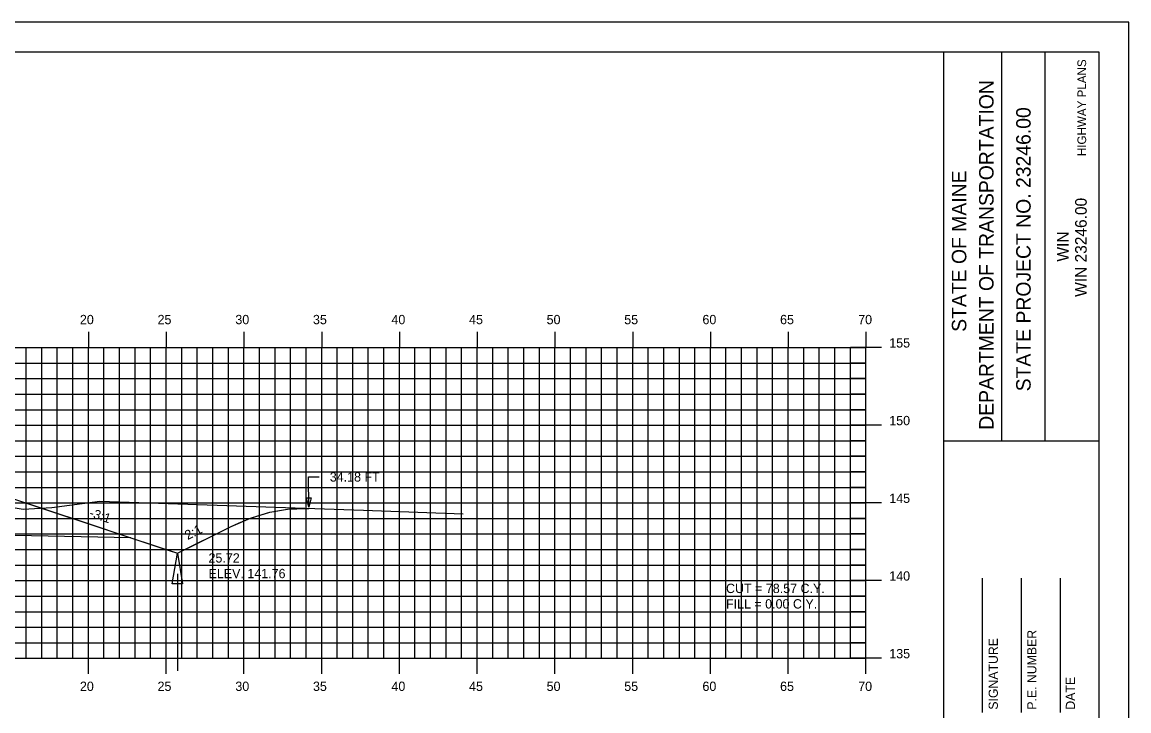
# Model space of a CAD drawing. Extents: x 1144751 to 1144921, y 608981 to 609091.
# Drawn here: x 1144849.4 to 1144920.5, y 609047 to 609091.3 of the extents above; entities that cross this region are included whole.
import ezdxf

# ---------------------------------------------------------------- set-up
doc = ezdxf.new("R2010")
doc.units = 0
for name, color, linetype in [('ANNOTATION', 7, 'Continuous'), ('BORDER', 7, 'Continuous'), ('D_Drainage_Ditch_Line', 7, 'Continuous'), ('D_Roadway_SlopeLines', 7, 'Continuous'), ('D_Roadway_SubGrade', 7, 'Continuous'), ('D_Text_Standard', 7, 'Continuous'), ('H_V ANNOTATION', 7, 'Continuous'), ('HIGHWAY_TITLE', 7, 'Continuous'), ('MAJOR', 7, 'Continuous'), ('MINOR', 7, 'Continuous'), ('PLOT BOUNDARY', 7, 'Continuous'), ('S_Roadway_Centerline', 7, 'Continuous')]:
    doc.layers.add(name, color=color, linetype=linetype)

msp = doc.modelspace()

# ---------------------------------------------------------------- linework, layer by layer
msp.add_lwpolyline([(1144848.619, 609060.668), (1144853.41, 609059.072), (1144856.342, 609058.094), (1144858.203, 609057.474), (1144859.342, 609057.094), (1144860.653, 609057.749), (1144862.796, 609058.821), (1144863.27, 609059.026), (1144864.046, 609059.362), (1144864.52, 609059.504), (1144865.296, 609059.737), (1144865.77, 609059.816), (1144866.546, 609059.945), (1144867.02, 609059.96), (1144867.796, 609059.986)])
at = {"layer": 'BORDER'}
for p, q in [((1144908.619, 608984.335), (1144908.619, 609089.335)), ((1144912.348, 609064.332), (1144912.348, 609089.332)), ((1144915.143, 609064.332), (1144915.143, 609089.332)), ((1144908.62, 609064.329), (1144918.619, 609064.329)), ((1144911.119, 609046.838), (1144911.119, 609055.485)), ((1144913.619, 609046.838), (1144913.619, 609055.485)), ((1144916.119, 609046.838), (1144916.119, 609055.485))]:
    msp.add_line(p, q, dxfattribs=at)
msp.add_lwpolyline([(1144758.619, 608984.335), (1144918.619, 608984.335), (1144918.619, 609089.335), (1144758.619, 609089.335)], close=True, dxfattribs=at)
at = {"layer": 'D_Drainage_Ditch_Line'}
msp.add_line((1144859.342, 609055.782), (1144859.342, 609049.538), dxfattribs=at)
msp.add_lwpolyline([(1144859.67, 609055.125), (1144859.014, 609055.125), (1144859.342, 609057.094)], close=True, dxfattribs=at)
at = {"layer": 'D_Roadway_SlopeLines'}
for points in [[(1144859.342, 609057.094), (1144862.796, 609058.821), (1144864.046, 609059.362), (1144865.296, 609059.737), (1144866.546, 609059.945), (1144867.796, 609059.986)], [(1144856.342, 609058.094), (1144859.342, 609057.094)]]:
    msp.add_lwpolyline(points, dxfattribs=at)
at = {"layer": 'D_Roadway_SubGrade'}
msp.add_lwpolyline([(1144844.619, 609060.412), (1144844.619, 609060.578), (1144848.619, 609060.418), (1144848.619, 609060.668), (1144848.619, 609060.668), (1144856.342, 609058.094), (1144844.619, 609058.328)], close=True, dxfattribs=at)
at = {"layer": 'D_Text_Standard'}
msp.add_lwpolyline([(1144867.796, 609060.071), (1144867.781, 609062.007), (1144868.461, 609062.007)], dxfattribs=at)
msp.add_lwpolyline([(1144867.796, 609060.071), (1144867.646, 609060.652), (1144867.937, 609060.654)], close=True, dxfattribs=at)
at = {"layer": 'MAJOR'}
for p, q in [((1144853.619, 609071.337), (1144853.619, 609070.335)), ((1144858.619, 609071.337), (1144858.619, 609070.335)), ((1144863.619, 609071.337), (1144863.619, 609070.335)), ((1144868.619, 609071.337), (1144868.619, 609070.335)), ((1144873.619, 609071.337), (1144873.619, 609070.335)), ((1144878.619, 609071.337), (1144878.619, 609070.335)), ((1144883.619, 609071.337), (1144883.619, 609070.335)), ((1144888.619, 609071.337), (1144888.619, 609070.335)), ((1144893.619, 609071.337), (1144893.619, 609070.335)), ((1144898.619, 609071.337), (1144898.619, 609070.335)), ((1144903.619, 609071.337), (1144903.619, 609070.335)), ((1144763.619, 609070.335), (1144903.619, 609070.335)), ((1144763.619, 609070.335), (1144903.619, 609070.335)), ((1144853.619, 609050.335), (1144853.619, 609070.335)), ((1144858.619, 609050.335), (1144858.619, 609070.335)), ((1144863.619, 609050.335), (1144863.619, 609070.335)), ((1144868.619, 609050.335), (1144868.619, 609070.335)), ((1144873.619, 609050.335), (1144873.619, 609070.335)), ((1144878.619, 609050.335), (1144878.619, 609070.335)), ((1144883.619, 609050.335), (1144883.619, 609070.335)), ((1144888.619, 609050.335), (1144888.619, 609070.335)), ((1144893.619, 609050.335), (1144893.619, 609070.335)), ((1144898.619, 609050.335), (1144898.619, 609070.335)), ((1144904.621, 609070.335), (1144902.617, 609070.335)), ((1144903.619, 609050.335), (1144903.619, 609070.335)), ((1144903.619, 609050.335), (1144903.619, 609070.335)), ((1144763.619, 609065.335), (1144903.619, 609065.335)), ((1144904.621, 609065.335), (1144902.617, 609065.335)), ((1144763.619, 609060.335), (1144903.619, 609060.335)), ((1144904.621, 609060.335), (1144902.617, 609060.335)), ((1144763.619, 609055.335), (1144903.619, 609055.335)), ((1144904.621, 609055.335), (1144902.617, 609055.335)), ((1144763.619, 609050.335), (1144903.619, 609050.335)), ((1144763.619, 609050.335), (1144903.619, 609050.335)), ((1144853.619, 609049.333), (1144853.619, 609050.335)), ((1144858.619, 609049.333), (1144858.619, 609050.335)), ((1144863.619, 609049.333), (1144863.619, 609050.335)), ((1144868.619, 609049.333), (1144868.619, 609050.335)), ((1144873.619, 609049.333), (1144873.619, 609050.335)), ((1144878.619, 609049.333), (1144878.619, 609050.335)), ((1144883.619, 609049.333), (1144883.619, 609050.335)), ((1144888.619, 609049.333), (1144888.619, 609050.335)), ((1144893.619, 609049.333), (1144893.619, 609050.335)), ((1144898.619, 609049.333), (1144898.619, 609050.335)), ((1144904.621, 609050.335), (1144902.617, 609050.335)), ((1144903.619, 609049.333), (1144903.619, 609050.335))]:
    msp.add_line(p, q, dxfattribs=at)
at = {"layer": 'MINOR'}
for p, q in [((1144849.619, 609050.335), (1144849.619, 609070.335)), ((1144850.619, 609050.335), (1144850.619, 609070.335)), ((1144851.619, 609050.335), (1144851.619, 609070.335)), ((1144852.619, 609050.335), (1144852.619, 609070.335)), ((1144854.619, 609050.335), (1144854.619, 609070.335)), ((1144855.619, 609050.335), (1144855.619, 609070.335)), ((1144856.619, 609050.335), (1144856.619, 609070.335)), ((1144857.619, 609050.335), (1144857.619, 609070.335)), ((1144859.619, 609050.335), (1144859.619, 609070.335)), ((1144860.619, 609050.335), (1144860.619, 609070.335)), ((1144861.619, 609050.335), (1144861.619, 609070.335)), ((1144862.619, 609050.335), (1144862.619, 609070.335)), ((1144864.619, 609050.335), (1144864.619, 609070.335)), ((1144865.619, 609050.335), (1144865.619, 609070.335)), ((1144866.619, 609050.335), (1144866.619, 609070.335)), ((1144867.619, 609050.335), (1144867.619, 609070.335)), ((1144869.619, 609050.335), (1144869.619, 609070.335)), ((1144870.619, 609050.335), (1144870.619, 609070.335)), ((1144871.619, 609050.335), (1144871.619, 609070.335)), ((1144872.619, 609050.335), (1144872.619, 609070.335)), ((1144874.619, 609050.335), (1144874.619, 609070.335)), ((1144875.619, 609050.335), (1144875.619, 609070.335)), ((1144876.619, 609050.335), (1144876.619, 609070.335)), ((1144877.619, 609050.335), (1144877.619, 609070.335)), ((1144879.619, 609050.335), (1144879.619, 609070.335)), ((1144880.619, 609050.335), (1144880.619, 609070.335)), ((1144881.619, 609050.335), (1144881.619, 609070.335)), ((1144882.619, 609050.335), (1144882.619, 609070.335)), ((1144884.619, 609050.335), (1144884.619, 609070.335)), ((1144885.619, 609050.335), (1144885.619, 609070.335)), ((1144886.619, 609050.335), (1144886.619, 609070.335)), ((1144887.619, 609050.335), (1144887.619, 609070.335)), ((1144889.619, 609050.335), (1144889.619, 609070.335)), ((1144890.619, 609050.335), (1144890.619, 609070.335)), ((1144891.619, 609050.335), (1144891.619, 609070.335)), ((1144892.619, 609050.335), (1144892.619, 609070.335)), ((1144894.619, 609050.335), (1144894.619, 609070.335)), ((1144895.619, 609050.335), (1144895.619, 609070.335)), ((1144896.619, 609050.335), (1144896.619, 609070.335)), ((1144897.619, 609050.335), (1144897.619, 609070.335)), ((1144899.619, 609050.335), (1144899.619, 609070.335)), ((1144900.619, 609050.335), (1144900.619, 609070.335)), ((1144901.619, 609050.335), (1144901.619, 609070.335)), ((1144902.619, 609050.335), (1144902.619, 609070.335)), ((1144763.619, 609069.335), (1144903.619, 609069.335)), ((1144903.619, 609069.335), (1144902.617, 609069.335)), ((1144763.619, 609068.335), (1144903.619, 609068.335)), ((1144903.619, 609068.335), (1144902.617, 609068.335)), ((1144763.619, 609067.335), (1144903.619, 609067.335)), ((1144903.619, 609067.335), (1144902.617, 609067.335)), ((1144763.619, 609066.335), (1144903.619, 609066.335)), ((1144903.619, 609066.335), (1144902.617, 609066.335)), ((1144763.619, 609064.335), (1144903.619, 609064.335)), ((1144903.619, 609064.335), (1144902.617, 609064.335)), ((1144763.619, 609063.335), (1144903.619, 609063.335)), ((1144903.619, 609063.335), (1144902.617, 609063.335)), ((1144763.619, 609062.335), (1144903.619, 609062.335)), ((1144903.619, 609062.335), (1144902.617, 609062.335)), ((1144763.619, 609061.335), (1144903.619, 609061.335)), ((1144903.619, 609061.335), (1144902.617, 609061.335)), ((1144763.619, 609059.335), (1144903.619, 609059.335)), ((1144903.619, 609059.335), (1144902.617, 609059.335)), ((1144763.619, 609058.335), (1144903.619, 609058.335)), ((1144903.619, 609058.335), (1144902.617, 609058.335)), ((1144763.619, 609057.335), (1144903.619, 609057.335)), ((1144903.619, 609057.335), (1144902.617, 609057.335)), ((1144763.619, 609056.335), (1144903.619, 609056.335)), ((1144903.619, 609056.335), (1144902.617, 609056.335)), ((1144763.619, 609054.335), (1144903.619, 609054.335)), ((1144903.619, 609054.335), (1144902.617, 609054.335)), ((1144763.619, 609053.335), (1144903.619, 609053.335)), ((1144903.619, 609053.335), (1144902.617, 609053.335)), ((1144763.619, 609052.335), (1144903.619, 609052.335)), ((1144903.619, 609052.335), (1144902.617, 609052.335)), ((1144763.619, 609051.335), (1144903.619, 609051.335)), ((1144903.619, 609051.335), (1144902.617, 609051.335))]:
    msp.add_line(p, q, dxfattribs=at)
at = {"layer": 'PLOT BOUNDARY'}
msp.add_lwpolyline([(1144750.526, 608981.276), (1144920.526, 608981.276), (1144920.526, 609091.276), (1144750.526, 609091.276)], close=True, dxfattribs=at)
at = {"layer": 'S_Roadway_Centerline'}
msp.add_lwpolyline([(1144783.122, 609061.95), (1144785.027, 609062.135), (1144787.81, 609062.15), (1144798.649, 609061.859), (1144806.19, 609061.719), (1144808.961, 609061.597), (1144814.062, 609061.329), (1144816.431, 609061.236), (1144817.427, 609061.225), (1144819.306, 609061.183), (1144824.536, 609061.274), (1144830.598, 609061.308), (1144839.021, 609060.925), (1144841.575, 609060.88), (1144845.067, 609060.537), (1144845.959, 609060.474), (1144846.963, 609060.332), (1144849.419, 609059.928), (1144851.267, 609060.05), (1144854.348, 609060.443), (1144871.318, 609059.866), (1144877.714, 609059.639)], dxfattribs=at)

# ---------------------------------------------------------------- texts
at = {"layer": 'ANNOTATION'}
for s, rotation, p in [('-3:1', 341.56521, (1144853.63, 609059.452)), ('2:1', 26.56505, (1144860.001, 609057.941))]:
    msp.add_text(s, height=0.6, rotation=rotation, dxfattribs=at).set_placement(p)
at = {"layer": 'BORDER'}
for s, height, p in [('DEPARTMENT OF TRANSPORTATION', 0.93176, (1144911.826, 609065.041)), ('STATE PROJECT NO. 23246.00', 0.93176, (1144914.211, 609067.517)), ('STATE OF MAINE', 0.93176, (1144910.074, 609071.347)), ('WIN 23246.00', 0.74527, (1144917.815, 609073.596)), ('WIN', 0.7453, (1144916.656, 609075.865)), ('P.E. NUMBER', 0.59055, (1144914.58, 609047.03)), ('SIGNATURE', 0.5906, (1144912.1, 609047.03)), ('DATE', 0.5906, (1144917.06, 609047.03))]:
    msp.add_text(s, height=height, rotation=90, dxfattribs=at).set_placement(p)
at = {"layer": 'D_Text_Standard'}
for s, p in [('34.18 FT', (1144869.141, 609061.707)), ('25.72', (1144861.342, 609056.494)), ('ELEV. 141.76', (1144861.342, 609055.492)), ('CUT = 78.57 C.Y.', (1144894.619, 609054.535)), ('FILL = 0.00 C.Y.', (1144894.619, 609053.539))]:
    msp.add_text(s, height=0.6, dxfattribs=at).set_placement(p)
at = {"layer": 'H_V ANNOTATION'}
for s, p in [('20', (1144853.073, 609071.835)), ('25', (1144858.065, 609071.835)), ('30', (1144863.068, 609071.835)), ('35', (1144868.06, 609071.835)), ('40', (1144873.105, 609071.835)), ('45', (1144878.097, 609071.835)), ('50', (1144883.084, 609071.835)), ('55', (1144888.076, 609071.835)), ('60', (1144893.105, 609071.835)), ('65', (1144898.097, 609071.835)), ('70', (1144903.121, 609071.835)), ('155', (1144905.119, 609070.335)), ('150', (1144905.119, 609065.335)), ('145', (1144905.119, 609060.335)), ('140', (1144905.119, 609055.335)), ('135', (1144905.119, 609050.335)), ('20', (1144853.073, 609048.235)), ('25', (1144858.065, 609048.235)), ('30', (1144863.068, 609048.235)), ('35', (1144868.06, 609048.235)), ('40', (1144873.105, 609048.235)), ('45', (1144878.097, 609048.235)), ('50', (1144883.084, 609048.235)), ('55', (1144888.076, 609048.235)), ('60', (1144893.105, 609048.235)), ('65', (1144898.097, 609048.235)), ('70', (1144903.121, 609048.235))]:
    msp.add_text(s, height=0.6, dxfattribs=at).set_placement(p)
at = {"layer": 'HIGHWAY_TITLE'}
msp.add_text('HIGHWAY PLANS', height=0.55901, rotation=90, dxfattribs=at).set_placement((1144917.777, 609082.65))

doc.saveas('drawing.dxf')
